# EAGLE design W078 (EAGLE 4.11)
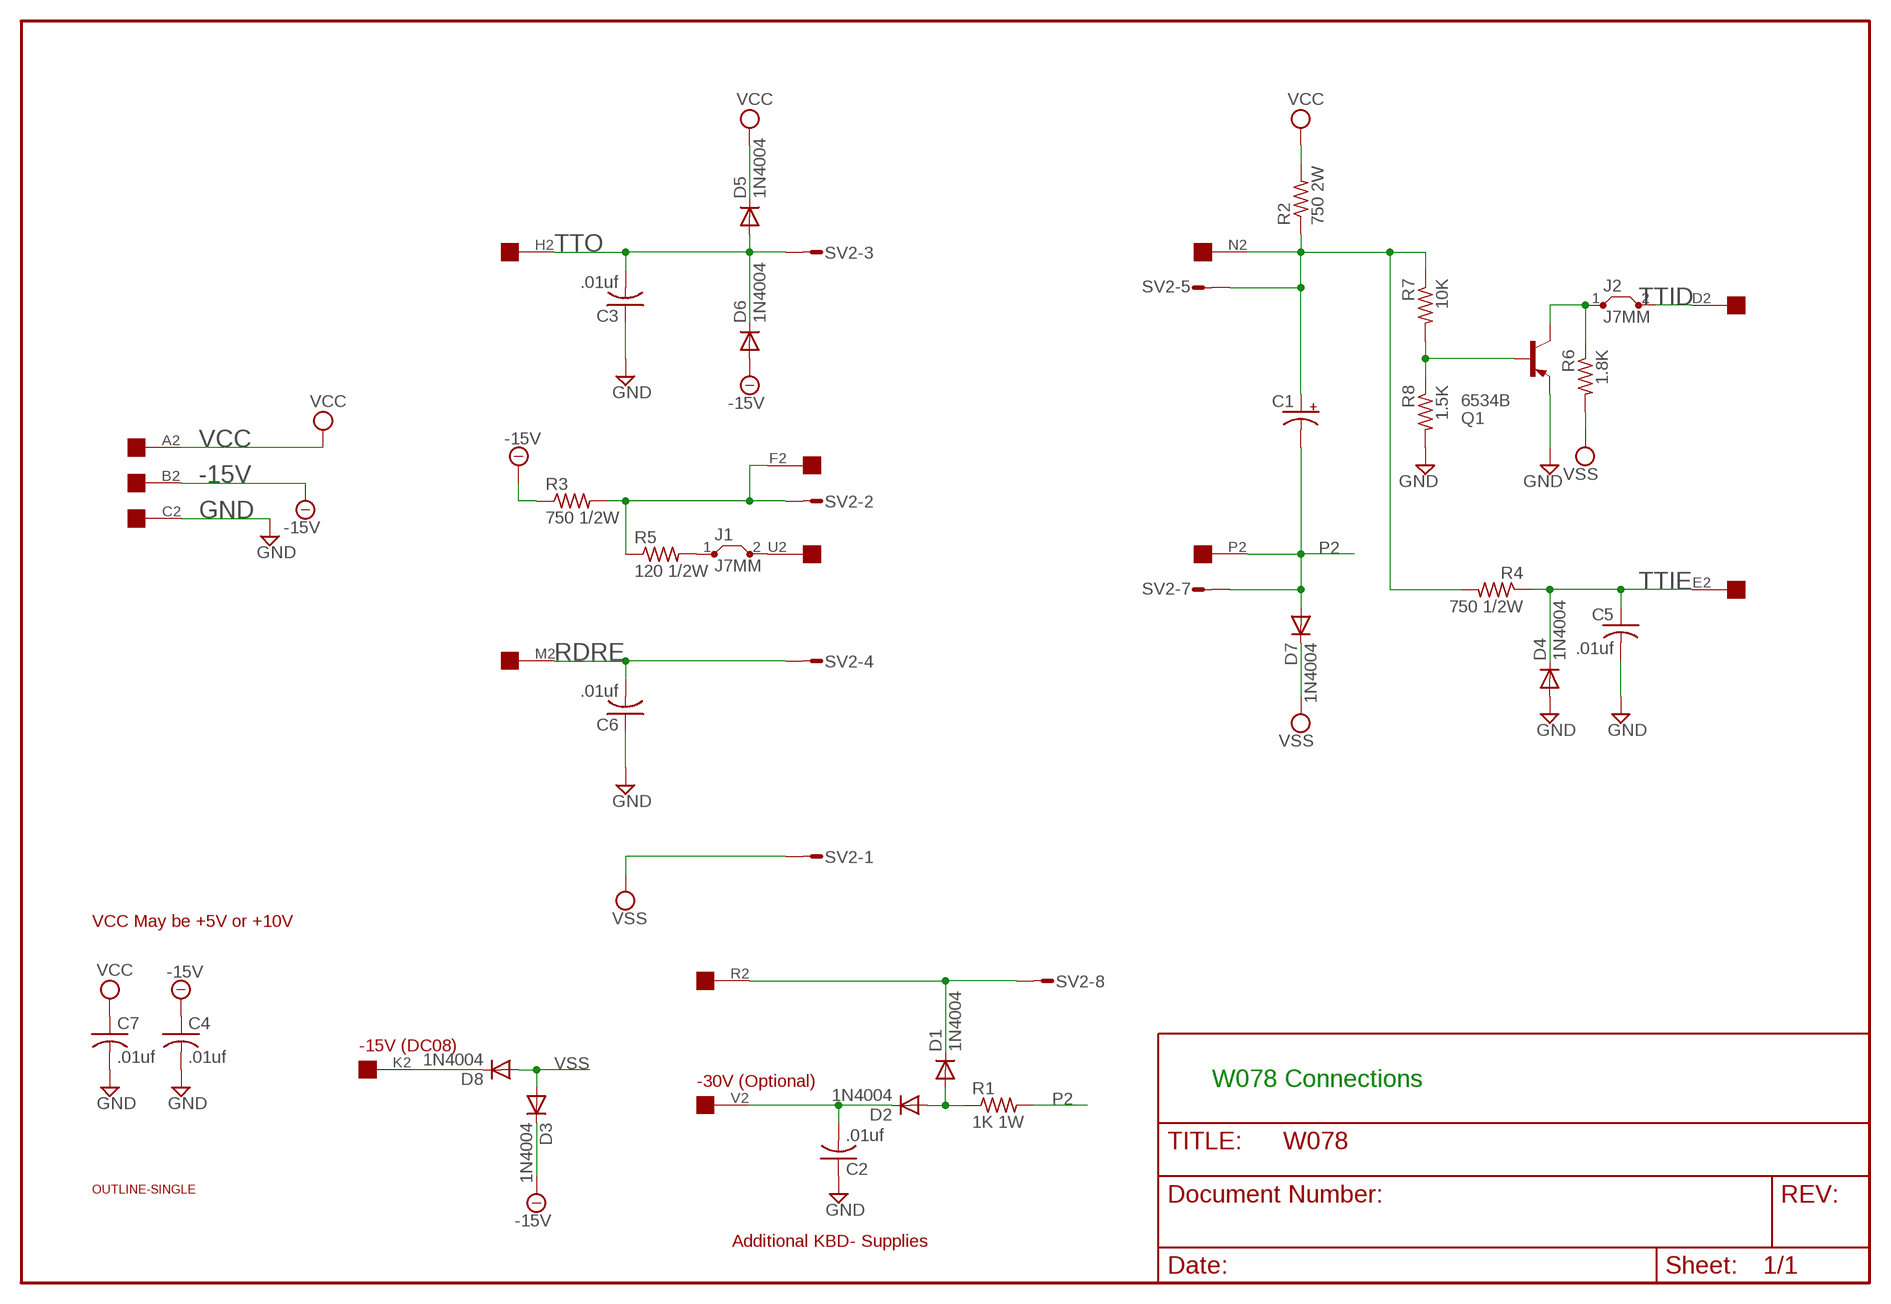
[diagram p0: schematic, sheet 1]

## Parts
C1  CPOL-USE22-6AXIAL  [E22-6]
C2  .01uf  C-US050-025X075  [C050-025X075]
C3  .01uf  C-US050-025X075  [C050-025X075]
C4  .01uf  C-US050-025X075  [C050-025X075]
C5  .01uf  C-US050-025X075  [C050-025X075]
C6  .01uf  C-US050-025X075  [C050-025X075]
C7  .01uf  C-US050-025X075  [C050-025X075]
D1  1N4004  1N4148  [DO35-10]
D2  1N4004  1N4148  [DO35-10]
D3  1N4004  1N4148  [DO35-10]
D4  1N4004  1N4148  [DO35-10]
D5  1N4004  1N4148  [DO35-10]
D6  1N4004  1N4148  [DO35-10]
D7  1N4004  1N4148  [DO35-10]
D8  1N4004  1N4148  [DO35-10]
EDGE  EDGE-1  [EDGE-CON1]
J1  J7MM  [07]
J2  J7MM  [07]
Q1  6534B  -PNP-TO92/  [TO92/]
R1  1K 1W  R-US_0411/15  [0411/15]
R2  750 2W  R-US_0411/15  [0411/15]
R3  750 1/2W  R-US_0309/12  [0309/12]
R4  750 1/2W  R-US_0309/12  [0309/12]
R5  120 1/2W  R-US_0309/12  [0309/12]
R6  1.8K  R-US_0207/10  [0207/10]
R7  10K  R-US_0207/10  [0207/10]
R8  1.5K  R-US_0207/10  [0207/10]
SV2  L08P  [L08P]
U$1  OUTLINE-SINGLE  [SINGLE]

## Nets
-15V: C4.1 D3.C D6.A EDGE.B2 R3.1
GND: C2.1 C3.1 C4.2 C5.2 C6.1 C7.2 D4.A EDGE.C2 Q1.1(E) R8.2
N$1: EDGE.F2 R3.2 R5.1 SV2.2
N$2: Q1.2(B) R7.2 R8.1
N$3: D1.C EDGE.R2 SV2.8
N$4: D8.C EDGE.K2
N$5: C2.2 D2.C EDGE.V2
N$6: D1.A D2.A R1.1
N$7: C1.+ EDGE.N2 R2.1 R4.2 R7.1 SV2.5
N$8: J1.1 R5.2
N$9: J2.1 Q1.3(C) R6.1
P2: C1.- D7.A EDGE.P2 R1.2 SV2.7
RDRE: C6.2 EDGE.M2 SV2.4
TTID: EDGE.D2 J2.2
TTIE: C5.1 D4.C EDGE.E2 R4.1
TTO: C3.2 D5.A D6.C EDGE.H2 SV2.3
TTOE: EDGE.U2 J1.2
VCC: C7.1 D5.C EDGE.A2 R2.2
VSS: D3.A D7.C D8.A R6.2 SV2.1
Unconnected: EDGE.J2 EDGE.L2 EDGE.S2 EDGE.T2 SV2.6

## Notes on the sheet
- VCC May be +5V or +10V
- -15V (DC08)
- -30V (Optional) | W078 Connections
- Additional KBD- Supplies

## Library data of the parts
C1 = rcl:CPOL-US: POLARIZED CAPACITOR, American symbol
C2-C7 = rcl:C-US: CAPACITOR, American symbol
D1-D8 = diode:1N4148: DIODE
EDGE = dec-con:EDGE-1: Single-Sided DEC Edge Connector -- (side 2)
J1 J2 = jumper:J: Bridge
Q1 = transistor:*-PNP-: PNP Transistror
R1-R8 = rcl:R-US_: RESISTOR, American symbol
SV2 = con-amp-mt:L08P: AMP MT CONNECTOR
U$1 = dec-con:OUTLINE-*: Board outlines for DEC boards.

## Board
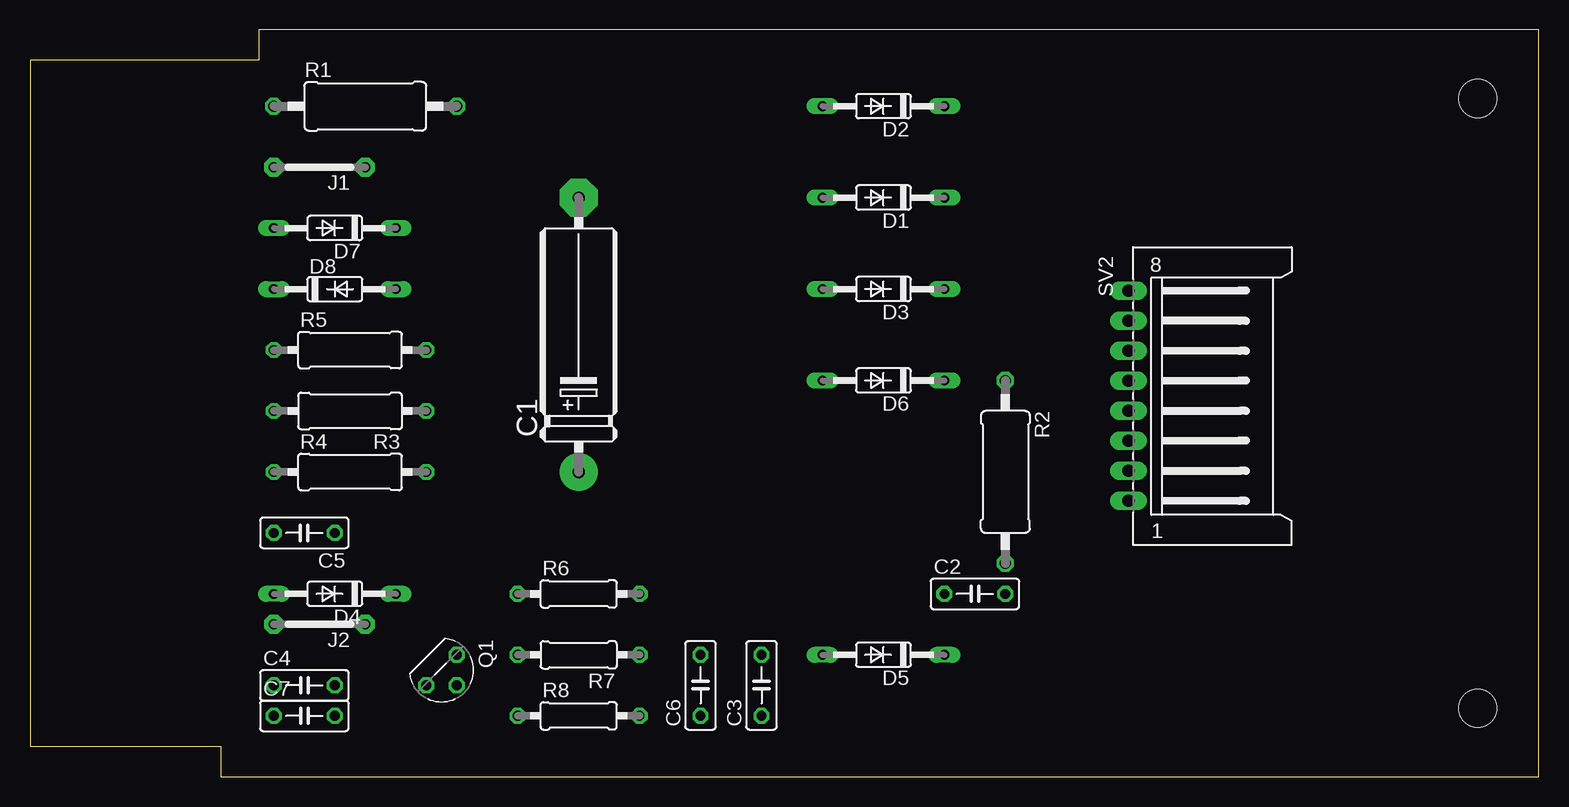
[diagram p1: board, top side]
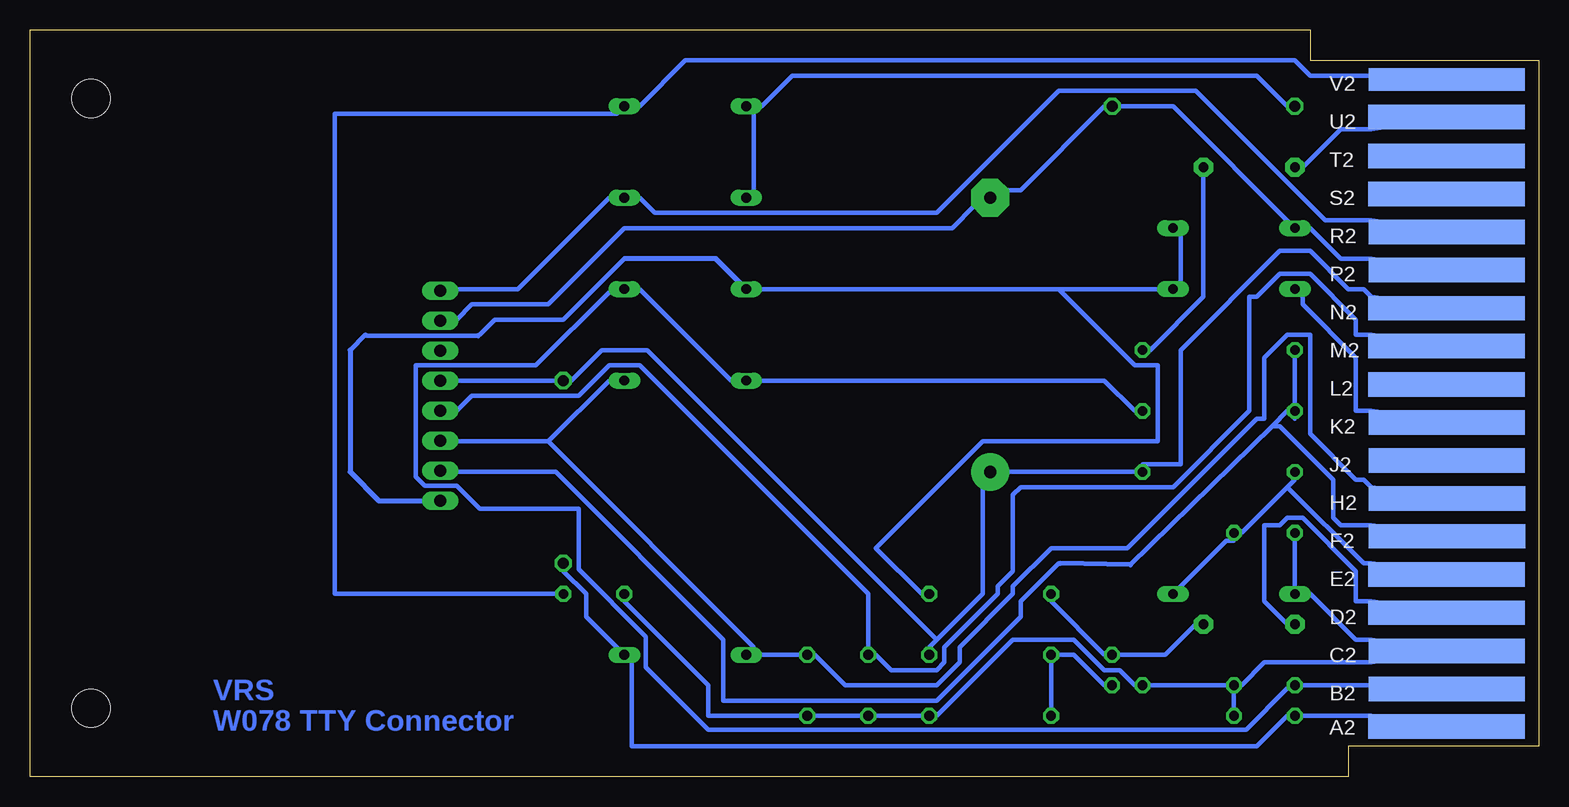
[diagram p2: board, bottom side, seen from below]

Size 125.73 x 62.23 mm. Coordinates in mm from the lower left corner, seen from the top.
Copper layers (1*16): Top 0.035mm / dielectric 1.5mm / Bottom 0.035mm
Design rules "15mils": minimum track width 15mil, minimum drill 24mil, track to track 15mil, track to pad 10mil, pad to pad 10mil, via to via 10mil, smd to smd 10mil, copper to edge 25mil, drill to drill 10mil, minimum pad ring 10mil, minimum via ring 8mil, stop-mask expansion 0mil, vias tented up to drill 0mil, thermal gap 10mil

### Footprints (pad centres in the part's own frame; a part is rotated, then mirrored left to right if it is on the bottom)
E22-6 = drill 1.016 pad 3.15 round: + -11.43,0 | drill 1.016 pad 3.15 octagon: - 11.43,0
C050-025X075 = drill 0.813 octagon: 1 -2.54,0; 2 2.54,0
DO35-10 = drill 0.813 long: A 5.08,0; C -5.08,0
EDGE-CON1 = smd 13.017 x 2.032 bottom: A2 7.69,4.194; B2 7.668,7.328; C2 7.668,10.49; D2 7.693,13.665; E2 7.693,16.84; F2 7.642,20.041; H2 7.642,23.19; J2 7.668,26.34; K2 7.668,29.515; L2 7.693,32.69; M2 7.693,35.89; N2 7.693,39.04; P2 7.668,42.24; R2 7.668,45.39; S2 7.693,48.565; T2 7.693,51.74; U2 7.693,54.966 | smd 13.017 x 1.905 bottom: V2 7.668,58.102
07 = drill 0.813 pad 1.6 octagon: 1 -3.81,0; 2 3.81,0
TO92/ = drill 0.813 octagon: 1 1.27,-1.27; 2 1.27,1.27; 3 -1.27,1.27
0411/15 = drill 0.914 octagon: 1 -7.62,0; 2 7.62,0
0309/12 = drill 0.813 octagon: 1 -6.35,0; 2 6.35,0
0207/10 = drill 0.813 octagon: 1 -5.08,0; 2 5.08,0
L08P = drill 1.016 long: 1 8.75,-6.25; 2 6.25,-6.25; 3 3.75,-6.25; 4 1.25,-6.25; 5 -1.25,-6.25; 6 -3.75,-6.25; 7 -6.25,-6.25; 8 -8.75,-6.25
SINGLE = hole 3.175: 120.65,56.515; 120.65,5.715

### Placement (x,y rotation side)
C1  45.72,36.83 90 top
C2  78.74,15.24 0 top
C3  60.96,7.62 90 top
C4  22.86,7.62 0 top
C5  22.86,20.32 180 top
C6  55.88,7.62 90 top
C7  22.86,5.08 0 top
D1  71.12,48.26 180 top
D2  71.12,55.88 180 top
D3  71.12,40.64 180 top
D4  25.4,15.24 180 top
D5  71.12,10.16 180 top
D6  71.12,33.02 180 top
D7  25.4,45.72 180 top
D8  25.4,40.64 0 top
EDGE  0,0 0 top
J1  24.13,50.8 180 top
J2  24.13,12.7 180 top
Q1  34.29,8.89 270 top
R1  27.94,55.88 0 top
R2  81.28,25.4 270 top
R3  26.67,30.48 180 top
R4  26.67,25.4 0 top
R5  26.67,35.56 0 top
R6  45.72,15.24 0 top
R7  45.72,10.16 180 top
R8  45.72,5.08 0 top
SV2  97.79,31.75 270 top
U$1  0,0 0 top

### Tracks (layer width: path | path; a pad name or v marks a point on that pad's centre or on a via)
-15V
  Bottom 0.381: R3.1 33.66,30.48 36.2,33.02 D6.A 67.31,33.02 74.93,40.64 D3.C 77.47,40.39 83.57,34.29 93.6,34.29 93.6,25.02 92.84,24.26 90.17,24.26 88.27,22.35 80.01,22.35 80.01,17.27 74.42,11.68 74.42,9.14 69.22,3.94 24.38,3.94 20.96,7.37 C4.1 13.97,7.62 EDGE.B2
GND
  Bottom 0.381: C4.2 Q1.1 33.66,7.62 34.93,8.89 36.2,8.89 38.74,11.43 43.82,11.43 50.17,5.08 R8.2 C6.1 C3.1 69.22,5.08 69.22,7.62 76.2,14.61 C2.1 | C5.2 D4.A 19.05,15.24 15.24,11.43 13.97,11.43 EDGE.C2 13.97,9.53 22.86,9.53 24.77,7.62 C4.2 | C4.2 C7.2
N$1
  Bottom 0.381: R3.2 R5.1 | 22.23,29.21 20.96,30.48 R3.2 | R3.2 20.32,29.84 | EDGE.F2 13.97,20.95 16.51,20.95 17.15,21.59 17.15,24.77 21.59,29.21 22.23,29.21 | 22.23,29.21 34.04,17.65 | SV2.2 90.17,25.4 81.92,25.4 67.95,11.43 67.95,6.35 50.17,6.35 43.18,13.34 43.18,14.61 40.01,17.78 39.88,17.78
  Bottom 0.406: 34.04,17.65 39.88,17.78
N$2
  Bottom 0.381: Q1.2 36.2,7.62 38.74,10.16 R7.2 R8.1
N$3
  Bottom 0.381: SV2.8 90.17,40.64 85.09,40.64 77.47,48.26 D1.C 74.93,48.26 73.66,46.99 50.17,46.99 40.01,57.15 28.58,57.15 17.78,46.35 13.97,46.35 EDGE.R2
N$4
  Bottom 0.381: D8.C 19.69,40.01 19.69,39.37 15.24,34.92 15.24,30.48 13.97,30.48 EDGE.K2
N$5
  Bottom 0.381: EDGE.V2 13.97,58.42 19.05,58.42 20.32,59.69 71.12,59.69 74.93,55.88 D2.C 76.84,55.24 100.33,55.24 100.33,15.24 C2.2
N$6
  Bottom 0.381: D1.A 65.41,48.9 65.41,55.24 D2.A 64.77,55.88 62.23,58.42 23.5,58.42 20.96,55.88 R1.1
N$7
  Bottom 0.381: EDGE.N2 13.97,40.01 14.61,40.64 15.88,40.64 19.05,43.81 21.59,43.81 29.85,35.56 29.85,26.04 33.02,26.04 R4.2 C1.+ 46.36,24.13 46.36,15.24 50.17,11.43 | 50.17,11.43 50.8,10.79 R7.1 | SV2.5 90.17,33.02 R2.1 80.65,33.02 78.11,35.56 74.3,35.56 50.17,11.43
N$8
  Bottom 0.381: R5.2 32.39,35.56 27.94,40.01 J1.1
N$9
  Bottom 0.381: R6.1 40.64,14.61 36.2,10.16 Q1.3 31.12,10.16 28.58,12.7 J2.1
P2
  Bottom 0.381: EDGE.P2 13.97,43.18 16.51,43.18 19.05,45.72 D7.A 30.48,55.88 R1.2 36.2,55.88 43.18,48.9 44.45,48.9 C1.- 46.99,47.62 48.9,45.72 76.2,45.72 82.55,39.37 88.9,39.37 90.17,38.1 SV2.7
RDRE
  Bottom 0.381: EDGE.M2 13.97,36.83 15.24,36.83 15.24,38.1 19.05,41.91 21.59,41.91 23.5,40.01 24.13,40.01 24.13,30.48 30.48,24.13 43.18,24.13 43.82,23.5 43.82,17.14 45.09,15.88 45.09,15.24 49.53,10.79 49.53,9.53 50.17,8.89 53.98,8.89 55.25,10.16 C6.2 55.88,15.24 74.93,34.29 77.47,34.29 80.01,31.75 88.9,31.75 90.17,30.48 SV2.4
TTID
  Bottom 0.381: J2.2 20.96,12.7 22.86,14.61 22.86,20.95 21.59,20.95 20.96,21.59 19.69,21.59 15.24,17.14 15.24,14.61 13.97,14.61 EDGE.D2
TTIE
  Bottom 0.381: D4.C 26.04,19.68 25.4,19.68 C5.1 24.77,20.32 20.96,24.13 | 20.96,24.13 20.32,24.77 R4.1 | 20.96,24.13 14.61,17.78 13.97,17.78 EDGE.E2
TTO
  Bottom 0.381: 82.55,27.94 77.47,33.02 D6.C | 82.55,27.94 90.17,27.94 SV2.3 | EDGE.H2 13.97,24.13 14.61,24.77 15.24,24.77 19.05,28.57 19.05,36.83 20.96,36.83 22.86,34.92 22.86,29.84 23.5,29.84 34.29,19.05 40.64,19.05 43.82,15.88 43.82,15.24 48.26,10.79 48.26,9.53 50.17,7.62 57.79,7.62 60.33,10.16 C3.2 D5.A 65.41,10.79 82.55,27.94
TTOE
  Bottom 0.381: J1.2 19.69,50.8 16.51,53.98 13.97,53.98 EDGE.U2
VCC
  Bottom 0.381: EDGE.A2 13.97,5.08 C7.1 20.96,5.08 23.5,2.54 75.57,2.54 75.57,9.53 D5.C 79.38,13.34 79.38,15.24 81.28,17.14 R2.2
VSS
  Bottom 0.381: D7.C 29.85,45.09 29.85,41.27 D8.A 40.01,40.64 | 40.01,40.64 D3.A | R6.2 51.44,15.24 55.25,19.05 46.36,27.94 31.75,27.94 31.75,34.29 33.66,34.29 40.01,40.64 | 99.06,35.56 97.79,36.83 97.61,36.75 88.57,36.75 | 88.57,36.75 88.39,36.7 | 76.2,43.18 81.28,38.1 87,38.1 88.27,36.83 88.57,36.75
  Bottom 0.406: SV2.1 96.66,23 99.06,25.4 99.06,35.56 | D3.A 68.58,43.18 76.2,43.18

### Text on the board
Bottom: VRS | W078 TTY Connector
